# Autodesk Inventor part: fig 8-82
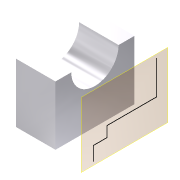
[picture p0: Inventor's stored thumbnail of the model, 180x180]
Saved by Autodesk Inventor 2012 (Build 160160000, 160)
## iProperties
Shininess: 77.0
Length Units: 11269
Angle Units: 11279
Time Units: 11290
Mass Units: 11283
Length Display Precision: 3
Angle Display Precision: 2
Created: 2002-01
Part Number: fig 8-82
Document SubType Name: Modeling
Designer: ***
Density: 1 g/cm^3
Material: Default
Density: 0.0
Volumn: 0.0
Area: 0.0
PropertySet Name: Model Information
Control State: 0
Master: False
Checked Out: False
Author: ***
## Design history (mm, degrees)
sketch "Sketch5"
  geometry: L1 (-22.226, 10.275)-(-14.226, 10.275); L2 (9.774, 10.275)-(17.774, 10.275); L3 (17.774, 10.275)-(17.774, -19.725); L4 (17.774, -19.725)-(-22.226, -19.725); L5 (-22.226, -19.725)-(-22.226, 10.275); A1 r 12 centre (-2.226, 10.275) between (-14.226, 10.275) and (9.774, 10.275)
  constraints: 10 end point, 2 equal length, 2 parallel, 2 point on circle, 1 centre point, 1 collinear, 1 horizontal, 1 perpendicular, 1 point on line
  dimensions: "d7" = 40 distance of L3.end L4.end; "d8" = 30 distance of L2.end L3.end; "d9" = 12 radius of A1
extrude "Extrusion2" new body sketch "Sketch5" distance "d10" = 20; taper "d11" = 0 deg
workplane "Work Plane3"
sketch "Sketch6"
  geometry: L1 (19.321, -18.091)-(12.314, -18.091); L2 (12.314, -18.091)-(12.314, -11.217); L3 (12.314, -11.217)-(7.026, -11.217); L4 (7.026, -11.217)-(7.026, 7.425); L5 (7.026, 7.425)-(7.026, 14.035); L6 (7.026, 14.035)-(-10.029, 14.035)
  constraints: 12 end point, 4 parallel, 1 horizontal, 1 perpendicular
body "Solid1"
other parameters: "d12" = 15
